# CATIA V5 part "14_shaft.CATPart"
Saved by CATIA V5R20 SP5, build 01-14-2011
Part number: 14_shaft
Bounding box of the stored display mesh (mm): x -9.487 to 9.487, y -70.354 to 45.862, z -9.487 to 9.487
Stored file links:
  C:\Documents and Settings\anizard\Bureau\13\14_shaft.CATPart
  C:\Documents and Settings\anizard\Bureau\13\anizard.CATProduct
  C:\Program Files (x86)\Dassault Systemes\B20\intel_a\reffiles\standard\MetricThickPitch.txt
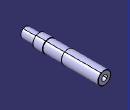
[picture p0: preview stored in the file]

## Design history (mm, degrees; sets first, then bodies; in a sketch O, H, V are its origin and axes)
Set1
  Plane1: linked copy from another document
  Line1: linked copy from another document
  Point1: linked copy from another document
  Plane2 to Plane6: linked copy from another document
Body1 (main body)
  Sketch1 on Plane1, origin (0, 0, 0), H (0, 1, 0), V (0, 0, 1)
    line L1 (45.8619, 0) -> (45.8619, 9.1714)
    point P2 (45.8619, 9.525)
    point P3 (45.8619, 9.525)
    line L2 (45.5084, 9.525) -> (-8, 9.525)
    point P4 (-8, 9.525)
    line L3 (-8, 9.525) -> (-8.5, 9.025)
    line L4 (-8.5, 9.025) -> (-35.5, 9.025)
    line L5 (-35.5, 9.025) -> (-36, 9.525)
    point P7 (-36, 9.525)
    line L6 (-36, 9.525) -> (-50, 9.525)
    point P8 (-50, 9.525)
    line L7 (-50, 9.525) -> (-50.3536, 9.1714)
    line L8 (-70.3536, 0) -> (45.8619, 0)
    reference projected line E1 (-76, 0) -> (64, 0) from Line1
    reference projected point E2 (0, 9.525) from Point1
    reference intersected line E3 through (-49, 0) direction (0, 1) from Plane3
    reference intersected line E4 through (-7, 0) direction (0, 1) from Plane4
    reference intersected line E5 through (-37, 0) direction (0, 1) from Plane5
    line L9 (45.8619, 9.1714) -> (45.5084, 9.525)
    line L10 (-50.3536, 9.1714) -> (-50.3536, 7)
    line L11 (-50.3536, 7) -> (-70.3536, 7)
    line L12 (-70.3536, 7) -> (-70.3536, 0)
    reference intersected line E6 through (46.8619, 0) direction (0, -1) from Plane6
    distance E3 P8 = 1
    distance L2 L4 = 0.5
    angle L5 L4 = 45
    angle L4 L3 = 45
    distance E4 P4 = 1
    distance E5 P7 = 1
    angle L1 L9 = 45
    length L9 = 0.5
    angle L7 L10 = 45
    length L7 = 0.5
    length L11 = 20
    distance L11 L8 = 7
    distance L1 E6 = 1
    vertical: L1 V, L10 V, L12 V
    horizontal: L2 H, L4 H, L6 H, L8 H, L11 H
    coincidence: L8 E1, L2 E2, L6 L2, P2 P3, L1 P2, L2 P3
  Shaft1: profile Sketch1, axis Line1, angle 360
  Sketch2 on face of Shaft1 from Sketch1.L1, origin (0, 45.8619, 0), H (1, 0, 0), V (0, 0, -1)
    point P1 (0, 0)
    reference projected point E1 (0, 0) from Line1
    coincidence: E1 P1
  Hole1: placed by Sketch2, at (0, 45.8619, 0) direction (0, -1, 0), diameter 8.376, depth 30, threaded "M10", thread diameter 10, thread depth 25, pitch 1.5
